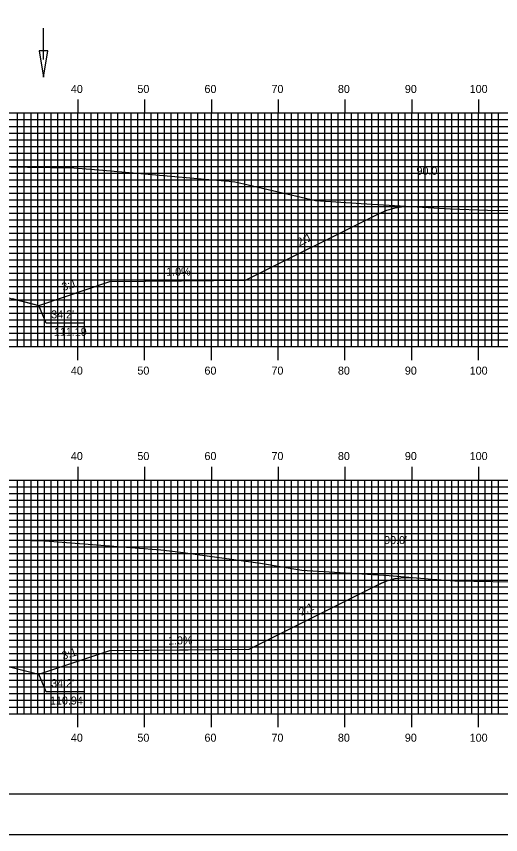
# Model space of a CAD drawing. Extents: x 1767694 to 1768037, y 442591 to 442811.
# Drawn here: x 1767890.3 to 1767962.8, y 442590.5 to 442713.1 of the extents above; entities that cross this region are included whole.
import ezdxf

# ---------------------------------------------------------------- set-up
doc = ezdxf.new("R2010")
doc.units = 0
for name, color, linetype in [('ANNOTATION', 7, 'Continuous'), ('BORDER', 7, 'Continuous'), ('D_Drainage_Ditch_Line', 7, 'Continuous'), ('D_Roadway_Centerline', 7, 'Continuous'), ('D_Roadway_SlopeLines', 7, 'Continuous'), ('D_Text_Standard', 7, 'Continuous'), ('H_V ANNOTATION', 7, 'Continuous'), ('MAJOR', 7, 'Continuous'), ('MINOR', 7, 'Continuous'), ('PLOT BOUNDARY', 7, 'Continuous'), ('S_Roadway_Centerline', 7, 'Continuous')]:
    doc.layers.add(name, color=color, linetype=linetype)

msp = doc.modelspace()

# ---------------------------------------------------------------- linework, layer by layer
at = {"layer": 'ANNOTATION'}
for points in [[(1767900.42, 442667.17), (1767894.73, 442667.17), (1767893.62, 442669.85)], [(1767900.42, 442611.92), (1767894.73, 442611.92), (1767893.62, 442614.6)]]:
    msp.add_lwpolyline(points, dxfattribs=at)
at = {"layer": 'BORDER'}
msp.add_lwpolyline([(1767709.85, 442596.67), (1768029.85, 442596.67), (1768029.85, 442806.67), (1767709.85, 442806.67)], close=True, dxfattribs=at)
at = {"layer": 'D_Drainage_Ditch_Line'}
msp.add_line((1767894.31, 442706.66), (1767894.31, 442711.36), dxfattribs=at)
msp.add_lwpolyline([(1767894.97, 442707.97), (1767893.66, 442707.97), (1767894.31, 442704.03)], close=True, dxfattribs=at)
at = {"layer": 'D_Roadway_Centerline'}
for points in [[(1767889.63, 442670.85), (1767893.62, 442669.85), (1767897.75, 442671.23), (1767904.25, 442673.4), (1767904.26, 442673.4), (1767914.98, 442673.5), (1767924.54, 442673.6), (1767924.54, 442673.6), (1767944.45, 442683.55), (1767944.45, 442683.55), (1767944.92, 442683.75), (1767945.7, 442684.09), (1767946.1, 442684.21), (1767946.95, 442684.45), (1767948.2, 442684.64), (1767949.45, 442684.66)], [(1767889.62, 442615.6), (1767893.62, 442614.6), (1767898.12, 442616.1), (1767904.25, 442618.15), (1767904.25, 442618.15), (1767915.97, 442618.26), (1767925.11, 442618.35), (1767925.11, 442618.35), (1767944.45, 442628.02), (1767944.45, 442628.02), (1767944.99, 442628.25), (1767945.7, 442628.56), (1767946.06, 442628.66), (1767946.95, 442628.91), (1767948.2, 442629.08), (1767948.69, 442629.07), (1767949.45, 442629.07)]]:
    msp.add_lwpolyline(points, dxfattribs=at)
at = {"layer": 'D_Roadway_SlopeLines'}
for points in [[(1767904.25, 442673.4), (1767924.54, 442673.6), (1767944.45, 442683.55), (1767945.7, 442684.09), (1767946.95, 442684.45), (1767948.2, 442684.64), (1767949.45, 442684.66)], [(1767879.45, 442673.4), (1767893.62, 442669.85)], [(1767893.62, 442669.85), (1767904.25, 442673.4)], [(1767904.25, 442618.15), (1767925.11, 442618.35), (1767944.45, 442628.02), (1767945.7, 442628.56), (1767946.95, 442628.91), (1767948.2, 442629.08), (1767949.45, 442629.07)], [(1767879.45, 442618.15), (1767893.62, 442614.6)], [(1767893.62, 442614.6), (1767904.25, 442618.15)]]:
    msp.add_lwpolyline(points, dxfattribs=at)
at = {"layer": 'MAJOR'}
for p, q in [((1767899.45, 442700.67), (1767899.45, 442698.67)), ((1767909.45, 442700.67), (1767909.45, 442698.67)), ((1767919.45, 442700.67), (1767919.45, 442698.67)), ((1767929.45, 442700.67), (1767929.45, 442698.67)), ((1767939.45, 442700.67), (1767939.45, 442698.67)), ((1767949.45, 442700.67), (1767949.45, 442698.67)), ((1767959.45, 442700.67), (1767959.45, 442698.67)), ((1767719.45, 442698.67), (1767999.45, 442698.67)), ((1767719.45, 442698.67), (1767999.45, 442698.67)), ((1767899.45, 442663.67), (1767899.45, 442698.67)), ((1767909.45, 442663.67), (1767909.45, 442698.67)), ((1767919.45, 442663.67), (1767919.45, 442698.67)), ((1767929.45, 442663.67), (1767929.45, 442698.67)), ((1767939.45, 442663.67), (1767939.45, 442698.67)), ((1767949.45, 442663.67), (1767949.45, 442698.67)), ((1767959.45, 442663.67), (1767959.45, 442698.67)), ((1767719.45, 442693.67), (1767999.45, 442693.67)), ((1767719.45, 442688.67), (1767999.45, 442688.67)), ((1767719.45, 442683.67), (1767999.45, 442683.67)), ((1767719.45, 442678.67), (1767999.45, 442678.67)), ((1767719.45, 442673.67), (1767999.45, 442673.67)), ((1767719.45, 442668.67), (1767999.45, 442668.67)), ((1767719.45, 442663.67), (1767999.45, 442663.67)), ((1767719.45, 442663.67), (1767999.45, 442663.67)), ((1767899.45, 442661.66), (1767899.45, 442663.67)), ((1767909.45, 442661.66), (1767909.45, 442663.67)), ((1767919.45, 442661.66), (1767919.45, 442663.67)), ((1767929.45, 442661.66), (1767929.45, 442663.67)), ((1767939.45, 442661.66), (1767939.45, 442663.67)), ((1767949.45, 442661.66), (1767949.45, 442663.67)), ((1767959.45, 442661.66), (1767959.45, 442663.67)), ((1767899.45, 442645.67), (1767899.45, 442643.67)), ((1767909.45, 442645.67), (1767909.45, 442643.67)), ((1767919.45, 442645.67), (1767919.45, 442643.67)), ((1767929.45, 442645.67), (1767929.45, 442643.67)), ((1767939.45, 442645.67), (1767939.45, 442643.67)), ((1767949.45, 442645.67), (1767949.45, 442643.67)), ((1767959.45, 442645.67), (1767959.45, 442643.67)), ((1767719.45, 442643.67), (1767999.45, 442643.67)), ((1767719.45, 442643.67), (1767999.45, 442643.67)), ((1767899.45, 442608.67), (1767899.45, 442643.67)), ((1767909.45, 442608.67), (1767909.45, 442643.67)), ((1767919.45, 442608.67), (1767919.45, 442643.67)), ((1767929.45, 442608.67), (1767929.45, 442643.67)), ((1767939.45, 442608.67), (1767939.45, 442643.67)), ((1767949.45, 442608.67), (1767949.45, 442643.67)), ((1767959.45, 442608.67), (1767959.45, 442643.67)), ((1767719.45, 442638.67), (1767999.45, 442638.67)), ((1767719.45, 442633.67), (1767999.45, 442633.67)), ((1767719.45, 442628.67), (1767999.45, 442628.67)), ((1767719.45, 442623.67), (1767999.45, 442623.67)), ((1767719.45, 442618.67), (1767999.45, 442618.67)), ((1767719.45, 442613.67), (1767999.45, 442613.67)), ((1767719.45, 442608.67), (1767999.45, 442608.67)), ((1767719.45, 442608.67), (1767999.45, 442608.67)), ((1767899.45, 442606.66), (1767899.45, 442608.67)), ((1767909.45, 442606.66), (1767909.45, 442608.67)), ((1767919.45, 442606.66), (1767919.45, 442608.67)), ((1767929.45, 442606.66), (1767929.45, 442608.67)), ((1767939.45, 442606.66), (1767939.45, 442608.67)), ((1767949.45, 442606.66), (1767949.45, 442608.67)), ((1767959.45, 442606.66), (1767959.45, 442608.67))]:
    msp.add_line(p, q, dxfattribs=at)
at = {"layer": 'MINOR'}
for p, q in [((1767890.45, 442663.67), (1767890.45, 442698.67)), ((1767891.45, 442663.67), (1767891.45, 442698.67)), ((1767892.45, 442663.67), (1767892.45, 442698.67)), ((1767893.45, 442663.67), (1767893.45, 442698.67)), ((1767894.45, 442663.67), (1767894.45, 442698.67)), ((1767895.45, 442663.67), (1767895.45, 442698.67)), ((1767896.45, 442663.67), (1767896.45, 442698.67)), ((1767897.45, 442663.67), (1767897.45, 442698.67)), ((1767898.45, 442663.67), (1767898.45, 442698.67)), ((1767900.45, 442663.67), (1767900.45, 442698.67)), ((1767901.45, 442663.67), (1767901.45, 442698.67)), ((1767902.45, 442663.67), (1767902.45, 442698.67)), ((1767903.45, 442663.67), (1767903.45, 442698.67)), ((1767904.45, 442663.67), (1767904.45, 442698.67)), ((1767905.45, 442663.67), (1767905.45, 442698.67)), ((1767906.45, 442663.67), (1767906.45, 442698.67)), ((1767907.45, 442663.67), (1767907.45, 442698.67)), ((1767908.45, 442663.67), (1767908.45, 442698.67)), ((1767910.45, 442663.67), (1767910.45, 442698.67)), ((1767911.45, 442663.67), (1767911.45, 442698.67)), ((1767912.45, 442663.67), (1767912.45, 442698.67)), ((1767913.45, 442663.67), (1767913.45, 442698.67)), ((1767914.45, 442663.67), (1767914.45, 442698.67)), ((1767915.45, 442663.67), (1767915.45, 442698.67)), ((1767916.45, 442663.67), (1767916.45, 442698.67)), ((1767917.45, 442663.67), (1767917.45, 442698.67)), ((1767918.45, 442663.67), (1767918.45, 442698.67)), ((1767920.45, 442663.67), (1767920.45, 442698.67)), ((1767921.45, 442663.67), (1767921.45, 442698.67)), ((1767922.45, 442663.67), (1767922.45, 442698.67)), ((1767923.45, 442663.67), (1767923.45, 442698.67)), ((1767924.45, 442663.67), (1767924.45, 442698.67)), ((1767925.45, 442663.67), (1767925.45, 442698.67)), ((1767926.45, 442663.67), (1767926.45, 442698.67)), ((1767927.45, 442663.67), (1767927.45, 442698.67)), ((1767928.45, 442663.67), (1767928.45, 442698.67)), ((1767930.45, 442663.67), (1767930.45, 442698.67)), ((1767931.45, 442663.67), (1767931.45, 442698.67)), ((1767932.45, 442663.67), (1767932.45, 442698.67)), ((1767933.45, 442663.67), (1767933.45, 442698.67)), ((1767934.45, 442663.67), (1767934.45, 442698.67)), ((1767935.45, 442663.67), (1767935.45, 442698.67)), ((1767936.45, 442663.67), (1767936.45, 442698.67)), ((1767937.45, 442663.67), (1767937.45, 442698.67)), ((1767938.45, 442663.67), (1767938.45, 442698.67)), ((1767940.45, 442663.67), (1767940.45, 442698.67)), ((1767941.45, 442663.67), (1767941.45, 442698.67)), ((1767942.45, 442663.67), (1767942.45, 442698.67)), ((1767943.45, 442663.67), (1767943.45, 442698.67)), ((1767944.45, 442663.67), (1767944.45, 442698.67)), ((1767945.45, 442663.67), (1767945.45, 442698.67)), ((1767946.45, 442663.67), (1767946.45, 442698.67)), ((1767947.45, 442663.67), (1767947.45, 442698.67)), ((1767948.45, 442663.67), (1767948.45, 442698.67)), ((1767950.45, 442663.67), (1767950.45, 442698.67)), ((1767951.45, 442663.67), (1767951.45, 442698.67)), ((1767952.45, 442663.67), (1767952.45, 442698.67)), ((1767953.45, 442663.67), (1767953.45, 442698.67)), ((1767954.45, 442663.67), (1767954.45, 442698.67)), ((1767955.45, 442663.67), (1767955.45, 442698.67)), ((1767956.45, 442663.67), (1767956.45, 442698.67)), ((1767957.45, 442663.67), (1767957.45, 442698.67)), ((1767958.45, 442663.67), (1767958.45, 442698.67)), ((1767960.45, 442663.67), (1767960.45, 442698.67)), ((1767961.45, 442663.67), (1767961.45, 442698.67)), ((1767962.45, 442663.67), (1767962.45, 442698.67)), ((1767719.45, 442697.67), (1767999.45, 442697.67)), ((1767719.45, 442696.67), (1767999.45, 442696.67)), ((1767719.45, 442695.67), (1767999.45, 442695.67)), ((1767719.45, 442694.67), (1767999.45, 442694.67)), ((1767719.45, 442692.67), (1767999.45, 442692.67)), ((1767719.45, 442691.67), (1767999.45, 442691.67)), ((1767719.45, 442690.67), (1767999.45, 442690.67)), ((1767719.45, 442689.67), (1767999.45, 442689.67)), ((1767719.45, 442687.67), (1767999.45, 442687.67)), ((1767719.45, 442686.67), (1767999.45, 442686.67)), ((1767719.45, 442685.67), (1767999.45, 442685.67)), ((1767719.45, 442684.67), (1767999.45, 442684.67)), ((1767719.45, 442682.67), (1767999.45, 442682.67)), ((1767719.45, 442681.67), (1767999.45, 442681.67)), ((1767719.45, 442680.67), (1767999.45, 442680.67)), ((1767719.45, 442679.67), (1767999.45, 442679.67)), ((1767719.45, 442677.67), (1767999.45, 442677.67)), ((1767719.45, 442676.67), (1767999.45, 442676.67)), ((1767719.45, 442675.67), (1767999.45, 442675.67)), ((1767719.45, 442674.67), (1767999.45, 442674.67)), ((1767719.45, 442672.67), (1767999.45, 442672.67)), ((1767719.45, 442671.67), (1767999.45, 442671.67)), ((1767719.45, 442670.67), (1767999.45, 442670.67)), ((1767719.45, 442669.67), (1767999.45, 442669.67)), ((1767719.45, 442667.67), (1767999.45, 442667.67)), ((1767719.45, 442666.67), (1767999.45, 442666.67)), ((1767719.45, 442665.67), (1767999.45, 442665.67)), ((1767719.45, 442664.67), (1767999.45, 442664.67)), ((1767890.45, 442608.67), (1767890.45, 442643.67)), ((1767891.45, 442608.67), (1767891.45, 442643.67)), ((1767892.45, 442608.67), (1767892.45, 442643.67)), ((1767893.45, 442608.67), (1767893.45, 442643.67)), ((1767894.45, 442608.67), (1767894.45, 442643.67)), ((1767895.45, 442608.67), (1767895.45, 442643.67)), ((1767896.45, 442608.67), (1767896.45, 442643.67)), ((1767897.45, 442608.67), (1767897.45, 442643.67)), ((1767898.45, 442608.67), (1767898.45, 442643.67)), ((1767900.45, 442608.67), (1767900.45, 442643.67)), ((1767901.45, 442608.67), (1767901.45, 442643.67)), ((1767902.45, 442608.67), (1767902.45, 442643.67)), ((1767903.45, 442608.67), (1767903.45, 442643.67)), ((1767904.45, 442608.67), (1767904.45, 442643.67)), ((1767905.45, 442608.67), (1767905.45, 442643.67)), ((1767906.45, 442608.67), (1767906.45, 442643.67)), ((1767907.45, 442608.67), (1767907.45, 442643.67)), ((1767908.45, 442608.67), (1767908.45, 442643.67)), ((1767910.45, 442608.67), (1767910.45, 442643.67)), ((1767911.45, 442608.67), (1767911.45, 442643.67)), ((1767912.45, 442608.67), (1767912.45, 442643.67)), ((1767913.45, 442608.67), (1767913.45, 442643.67)), ((1767914.45, 442608.67), (1767914.45, 442643.67)), ((1767915.45, 442608.67), (1767915.45, 442643.67)), ((1767916.45, 442608.67), (1767916.45, 442643.67)), ((1767917.45, 442608.67), (1767917.45, 442643.67)), ((1767918.45, 442608.67), (1767918.45, 442643.67)), ((1767920.45, 442608.67), (1767920.45, 442643.67)), ((1767921.45, 442608.67), (1767921.45, 442643.67)), ((1767922.45, 442608.67), (1767922.45, 442643.67)), ((1767923.45, 442608.67), (1767923.45, 442643.67)), ((1767924.45, 442608.67), (1767924.45, 442643.67)), ((1767925.45, 442608.67), (1767925.45, 442643.67)), ((1767926.45, 442608.67), (1767926.45, 442643.67)), ((1767927.45, 442608.67), (1767927.45, 442643.67)), ((1767928.45, 442608.67), (1767928.45, 442643.67)), ((1767930.45, 442608.67), (1767930.45, 442643.67)), ((1767931.45, 442608.67), (1767931.45, 442643.67)), ((1767932.45, 442608.67), (1767932.45, 442643.67)), ((1767933.45, 442608.67), (1767933.45, 442643.67)), ((1767934.45, 442608.67), (1767934.45, 442643.67)), ((1767935.45, 442608.67), (1767935.45, 442643.67)), ((1767936.45, 442608.67), (1767936.45, 442643.67)), ((1767937.45, 442608.67), (1767937.45, 442643.67)), ((1767938.45, 442608.67), (1767938.45, 442643.67)), ((1767940.45, 442608.67), (1767940.45, 442643.67)), ((1767941.45, 442608.67), (1767941.45, 442643.67)), ((1767942.45, 442608.67), (1767942.45, 442643.67)), ((1767943.45, 442608.67), (1767943.45, 442643.67)), ((1767944.45, 442608.67), (1767944.45, 442643.67)), ((1767945.45, 442608.67), (1767945.45, 442643.67)), ((1767946.45, 442608.67), (1767946.45, 442643.67)), ((1767947.45, 442608.67), (1767947.45, 442643.67)), ((1767948.45, 442608.67), (1767948.45, 442643.67)), ((1767950.45, 442608.67), (1767950.45, 442643.67)), ((1767951.45, 442608.67), (1767951.45, 442643.67)), ((1767952.45, 442608.67), (1767952.45, 442643.67)), ((1767953.45, 442608.67), (1767953.45, 442643.67)), ((1767954.45, 442608.67), (1767954.45, 442643.67)), ((1767955.45, 442608.67), (1767955.45, 442643.67)), ((1767956.45, 442608.67), (1767956.45, 442643.67)), ((1767957.45, 442608.67), (1767957.45, 442643.67)), ((1767958.45, 442608.67), (1767958.45, 442643.67)), ((1767960.45, 442608.67), (1767960.45, 442643.67)), ((1767961.45, 442608.67), (1767961.45, 442643.67)), ((1767962.45, 442608.67), (1767962.45, 442643.67)), ((1767719.45, 442642.67), (1767999.45, 442642.67)), ((1767719.45, 442641.67), (1767999.45, 442641.67)), ((1767719.45, 442640.67), (1767999.45, 442640.67)), ((1767719.45, 442639.67), (1767999.45, 442639.67)), ((1767719.45, 442637.67), (1767999.45, 442637.67)), ((1767719.45, 442636.67), (1767999.45, 442636.67)), ((1767719.45, 442635.67), (1767999.45, 442635.67)), ((1767719.45, 442634.67), (1767999.45, 442634.67)), ((1767719.45, 442632.67), (1767999.45, 442632.67)), ((1767719.45, 442631.67), (1767999.45, 442631.67)), ((1767719.45, 442630.67), (1767999.45, 442630.67)), ((1767719.45, 442629.67), (1767999.45, 442629.67)), ((1767719.45, 442627.67), (1767999.45, 442627.67)), ((1767719.45, 442626.67), (1767999.45, 442626.67)), ((1767719.45, 442625.67), (1767999.45, 442625.67)), ((1767719.45, 442624.67), (1767999.45, 442624.67)), ((1767719.45, 442622.67), (1767999.45, 442622.67)), ((1767719.45, 442621.67), (1767999.45, 442621.67)), ((1767719.45, 442620.67), (1767999.45, 442620.67)), ((1767719.45, 442619.67), (1767999.45, 442619.67)), ((1767719.45, 442617.67), (1767999.45, 442617.67)), ((1767719.45, 442616.67), (1767999.45, 442616.67)), ((1767719.45, 442615.67), (1767999.45, 442615.67)), ((1767719.45, 442614.67), (1767999.45, 442614.67)), ((1767719.45, 442612.67), (1767999.45, 442612.67)), ((1767719.45, 442611.67), (1767999.45, 442611.67)), ((1767719.45, 442610.67), (1767999.45, 442610.67)), ((1767719.45, 442609.67), (1767999.45, 442609.67))]:
    msp.add_line(p, q, dxfattribs=at)
at = {"layer": 'PLOT BOUNDARY'}
msp.add_lwpolyline([(1767693.66, 442590.55), (1768033.66, 442590.55), (1768033.66, 442810.55), (1767693.66, 442810.55)], close=True, dxfattribs=at)
at = {"layer": 'S_Roadway_Centerline'}
for points in [[(1767886.88, 442690.66), (1767891.9, 442690.55), (1767898.86, 442690.44), (1767903.21, 442690.12), (1767919.08, 442688.7), (1767922.1, 442688.44), (1767922.94, 442688.37), (1767924.29, 442688.06), (1767935.06, 442685.57), (1767941.89, 442685.1), (1767955.26, 442684.32), (1767960.79, 442684.13), (1767968.85, 442684.06), (1767979.13, 442683.94), (1767986.66, 442683.83), (1767999.45, 442683.63)], [(1767880.33, 442634.9), (1767894.58, 442634.55), (1767904.18, 442633.83), (1767911.9, 442633.23), (1767914.49, 442632.9), (1767926.83, 442631.21), (1767932.98, 442630.16), (1767946.05, 442629.35), (1767952.52, 442628.81), (1767955.89, 442628.55), (1767967.31, 442628.36), (1767971.79, 442628.27), (1767978, 442628.15), (1767990.79, 442627.93), (1767993.95, 442627.91), (1767999.45, 442627.7)]]:
    msp.add_lwpolyline(points, dxfattribs=at)

# ---------------------------------------------------------------- texts
at = {"layer": 'ANNOTATION'}
for s, rotation, p in [('2:1', 26.5655, (1767932.64, 442678.68)), ('1.0%', 0.5704, (1767912.69, 442674.28)), ('3:1', 18.437, (1767897.28, 442671.98)), ('2:1', 26.5658, (1767932.93, 442623.3)), ('1.0%', 0.5713, (1767912.97, 442619.03)), ('3:1', 18.437, (1767897.28, 442616.73))]:
    msp.add_text(s, height=1.2, rotation=rotation, dxfattribs=at).set_placement(p)
for s, p in [("34.2'", (1767895.47, 442667.89)), ('111.19', (1767895.88, 442665.29)), ("34.2'", (1767895.47, 442612.64)), ('110.94', (1767895.3, 442610.04))]:
    msp.add_text(s, height=1.2, dxfattribs=at).set_placement(p)
at = {"layer": 'D_Text_Standard'}
for p in [(1767950.16, 442689.41), (1767945.32, 442634.08)]:
    msp.add_text("90.0'", height=1.2, dxfattribs=at).set_placement(p)
at = {"layer": 'H_V ANNOTATION'}
for s, p in [('40', (1767898.42, 442701.67)), ('50', (1767908.38, 442701.67)), ('60', (1767918.42, 442701.67)), ('70', (1767928.45, 442701.67)), ('80', (1767938.4, 442701.67)), ('90', (1767948.42, 442701.67)), ('100', (1767958.13, 442701.67)), ('40', (1767898.42, 442659.47)), ('50', (1767908.38, 442659.47)), ('60', (1767918.42, 442659.47)), ('70', (1767928.45, 442659.47)), ('80', (1767938.4, 442659.47)), ('90', (1767948.42, 442659.47)), ('100', (1767958.13, 442659.47)), ('40', (1767898.42, 442646.67)), ('50', (1767908.38, 442646.67)), ('60', (1767918.42, 442646.67)), ('70', (1767928.45, 442646.67)), ('80', (1767938.4, 442646.67)), ('90', (1767948.42, 442646.67)), ('100', (1767958.13, 442646.67)), ('40', (1767898.42, 442604.47)), ('50', (1767908.38, 442604.47)), ('60', (1767918.42, 442604.47)), ('70', (1767928.45, 442604.47)), ('80', (1767938.4, 442604.47)), ('90', (1767948.42, 442604.47)), ('100', (1767958.13, 442604.47))]:
    msp.add_text(s, height=1.2, dxfattribs=at).set_placement(p)

doc.saveas('drawing.dxf')
